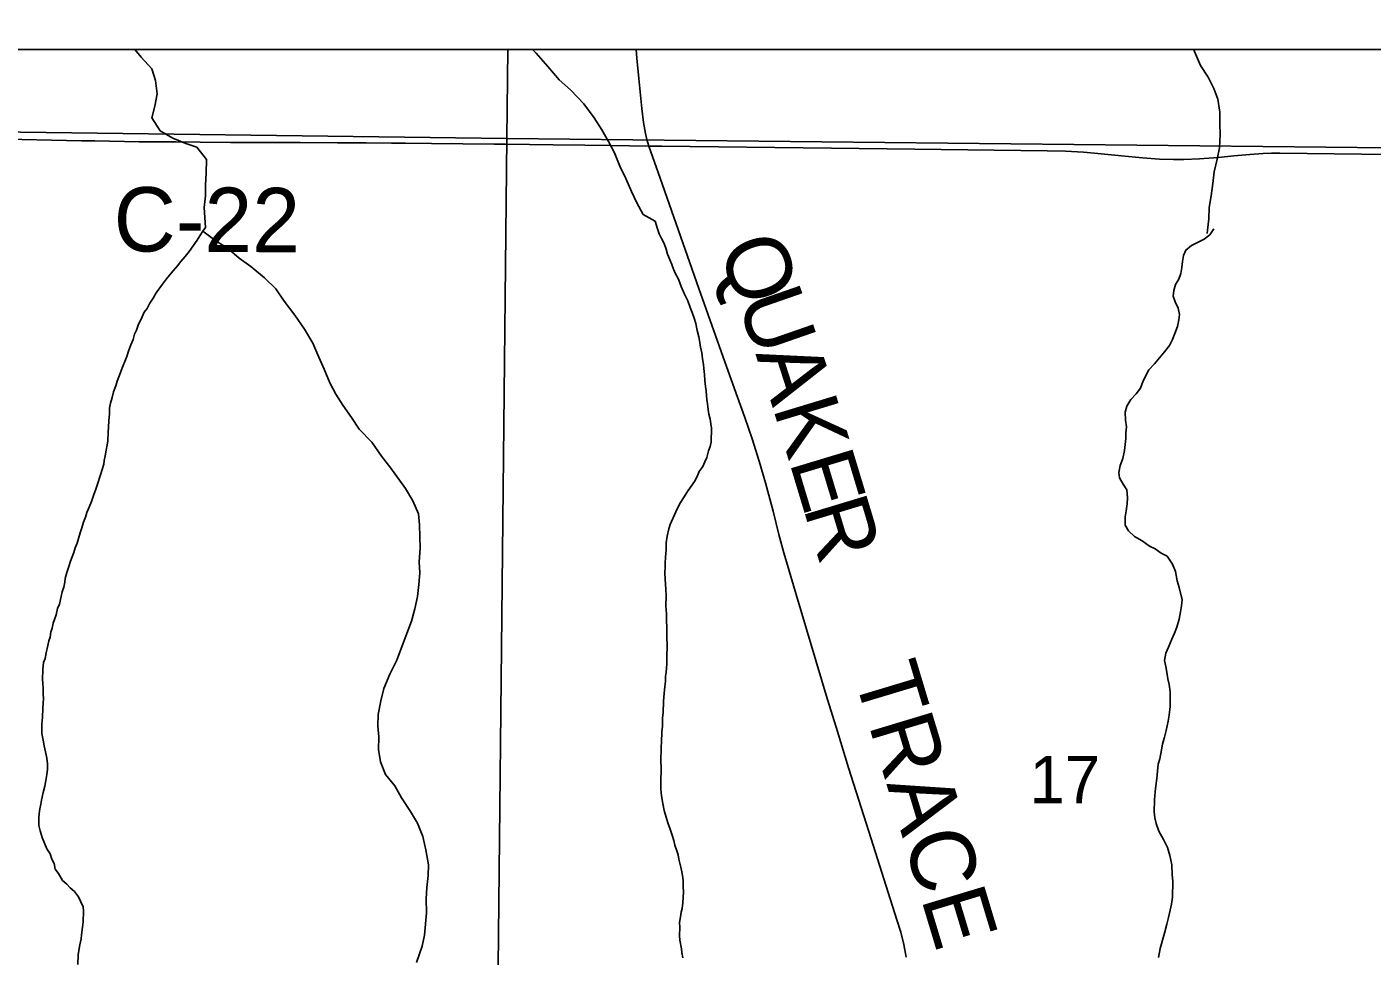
# Model space of a CAD drawing. Extents: x -8.8 to 41.4, y 0 to 34.6.
# Drawn here: x 5.925 to 7.113, y 15.817 to 16.638 of the extents above; entities that cross this region are included whole.
import ezdxf

# ---------------------------------------------------------------- set-up
doc = ezdxf.new("R2010")
doc.units = 0
for name, color, linetype in [('GM_X_Corporation', 7, 'Continuous'), ('GM_X_County_Road', 7, 'Continuous'), ('GM_X_Minor_River', 7, 'Continuous'), ('GM_X_Township_Road_Text', 7, 'Continuous'), ('GM_X_Township_Text', 7, 'Continuous'), ('SH_Data', 7, 'Continuous')]:
    doc.layers.add(name, color=color, linetype=linetype)

msp = doc.modelspace()

# ---------------------------------------------------------------- linework, layer by layer
at = {"layer": 'GM_X_Corporation'}
for points in [[(6.3498, 16.6176), (6.3489, 16.539), (5.354, 16.5519), (5.3707, 17.5614), (6.3609, 17.5464), (6.355, 17.0515)], [(7.3522, 16.6176), (7.351, 16.5283), (6.3489, 16.539), (6.3498, 16.6176)]]:
    msp.add_lwpolyline(points, dxfattribs=at)
for points in [[(5.354, 16.5519), (6.3489, 16.539), (6.3374, 15.4422), (5.3392, 15.4586), (5.3394, 15.5503)], [(6.3489, 16.539), (7.351, 16.5283), (7.3307, 15.4293), (6.3374, 15.4422)]]:
    msp.add_lwpolyline(points, close=True, dxfattribs=at)
at = {"layer": 'GM_X_County_Road'}
for points in [[(6.4745, 16.5323), (6.4727, 16.538), (6.4714, 16.5433), (6.4698, 16.5531), (6.4682, 16.5654), (6.4655, 16.5919), (6.464, 16.6099), (6.4634, 16.6176)], [(5.8938, 16.5388), (5.9733, 16.537), (5.9851, 16.5368), (6.0242, 16.5362), (6.0565, 16.5361), (6.0782, 16.5358), (6.1049, 16.5356), (6.1515, 16.5355), (6.1664, 16.5355), (6.1993, 16.5353), (6.2248, 16.5352), (6.2472, 16.535), (6.2596, 16.5349), (6.2826, 16.5347), (6.3379, 16.534), (6.3478, 16.5339), (6.3689, 16.5337), (6.39, 16.5334), (6.418, 16.5331), (6.4402, 16.5328), (6.4745, 16.5323), (6.486, 16.5322), (6.6357, 16.5305), (6.7096, 16.5296), (6.8264, 16.5281), (6.8425, 16.5277), (6.8586, 16.5268), (6.871, 16.5258), (6.892, 16.5236), (6.9106, 16.5218), (6.9255, 16.5209), (6.9379, 16.5205), (6.9472, 16.5206), (6.9609, 16.5211), (6.9777, 16.5223), (6.9913, 16.5236), (7.0055, 16.5249), (7.0172, 16.5257), (7.0246, 16.526), (7.032, 16.5261), (7.1041, 16.5251), (7.1649, 16.5244)], [(6.7017, 15.8162), (6.6998, 15.8274), (6.6971, 15.8382), (6.6936, 15.849), (6.6688, 15.9271), (6.651, 15.9834), (6.641, 16.0154), (6.6312, 16.0475), (6.6045, 16.1362), (6.5938, 16.1731), (6.5894, 16.1893), (6.5843, 16.2098), (6.5775, 16.235), (6.5719, 16.2541), (6.5658, 16.2737), (6.5594, 16.2926), (6.5529, 16.3107), (6.5417, 16.3417), (6.5186, 16.4066), (6.4844, 16.504), (6.4745, 16.5323)]]:
    msp.add_lwpolyline(points, dxfattribs=at)
at = {"layer": 'GM_X_Minor_River'}
msp.add_line((6.0203, 16.6176), (6.0261, 16.6107), dxfattribs=at)
for points in [[(6.3716, 16.6176), (6.3749, 16.6144), (6.3853, 16.6025), (6.3953, 16.5909), (6.4054, 16.582), (6.417, 16.5697), (6.4262, 16.5573), (6.4328, 16.5466), (6.4387, 16.5363), (6.4442, 16.5263), (6.4489, 16.5145), (6.4541, 16.5037), (6.4592, 16.4923), (6.4639, 16.4823), (6.4694, 16.472), (6.4801, 16.466)], [(6.9559, 16.6176), (6.9566, 16.6157), (6.9617, 16.6035), (6.9687, 16.5931), (6.9735, 16.5832), (6.9771, 16.5736), (6.9788, 16.5622), (6.979, 16.552), (6.9792, 16.5425), (6.9786, 16.5307), (6.9765, 16.5209), (6.974, 16.5096), (6.9727, 16.4994), (6.9714, 16.4884), (6.9696, 16.4782), (6.9691, 16.468), (6.9681, 16.4581), (6.9677, 16.4551)], [(6.0261, 16.6107), (6.0354, 16.6006), (6.0387, 16.5903), (6.04, 16.5785), (6.0379, 16.5676), (6.0354, 16.5574), (6.0428, 16.5459), (6.054, 16.5392), (6.0653, 16.5345), (6.0751, 16.5313), (6.0837, 16.5205), (6.0834, 16.5084), (6.0829, 16.4981), (6.0827, 16.4883), (6.0817, 16.4781)], [(5.996, 16.2684), (5.9965, 16.2718), (5.9967, 16.2801), (5.9972, 16.2839), (5.9974, 16.29), (5.9979, 16.2957), (5.9981, 16.301), (5.999, 16.3052), (6.0003, 16.3104), (6.0015, 16.3153), (6.0036, 16.3206), (6.0048, 16.3247), (6.0069, 16.33), (6.0081, 16.3334), (6.0102, 16.3387), (6.0114, 16.342), (6.0134, 16.3465), (6.0147, 16.3511), (6.0167, 16.3567), (6.0188, 16.3616), (6.02, 16.3661), (6.0217, 16.3699), (6.0237, 16.3751), (6.0261, 16.3796), (6.0286, 16.3856), (6.0313, 16.389), (6.0337, 16.3935), (6.0365, 16.3979), (6.0393, 16.4028), (6.0448, 16.4103), (6.0484, 16.4151), (6.0511, 16.4184), (6.0543, 16.4221), (6.0582, 16.4266), (6.0609, 16.4303), (6.0649, 16.4348), (6.0684, 16.4392), (6.0755, 16.4493), (6.0779, 16.453), (6.0803, 16.4571), (6.0827, 16.4605), (6.0817, 16.4781)], [(6.4801, 16.466), (6.4822, 16.4591)], [(6.0803, 16.4571), (6.0921, 16.4484), (6.1018, 16.4424), (6.1125, 16.4334), (6.1229, 16.4259), (6.1348, 16.416), (6.1448, 16.4063), (6.1524, 16.3954), (6.1616, 16.383), (6.1703, 16.3706), (6.1776, 16.3582), (6.1829, 16.3459), (6.1876, 16.3352), (6.1925, 16.3232), (6.1979, 16.3132), (6.2041, 16.3035), (6.2118, 16.2927), (6.2187, 16.2822), (6.2298, 16.2709), (6.2382, 16.2585), (6.2466, 16.248), (6.2594, 16.2298), (6.2659, 16.219), (6.2709, 16.2075), (6.2718, 16.198), (6.2722, 16.1873), (6.2723, 16.1774), (6.2716, 16.1653), (6.2721, 16.1554), (6.2714, 16.1452), (6.27, 16.1346), (6.2678, 16.1236), (6.2648, 16.1127), (6.2558, 16.0886), (6.2517, 16.0785), (6.2457, 16.0661), (6.2404, 16.0534), (6.2378, 16.0424), (6.2352, 16.0303), (6.2349, 16.0205), (6.2358, 16.0106), (6.2355, 15.9996), (6.2375, 15.9885), (6.2417, 15.9774), (6.2501, 15.9673), (6.2559, 15.9568), (6.2639, 15.9448), (6.2701, 15.9344), (6.2747, 15.9225), (6.2774, 15.911), (6.2797, 15.8977), (6.2794, 15.8882), (6.2784, 15.8776), (6.2777, 15.8677), (6.2781, 15.8552), (6.2764, 15.8355), (6.2743, 15.8257), (6.2693, 15.8114)], [(6.4822, 16.4591), (6.4836, 16.4549), (6.4857, 16.4506), (6.4879, 16.4464), (6.4897, 16.4414), (6.491, 16.4368), (6.4932, 16.4314), (6.4949, 16.4276), (6.4964, 16.4237), (6.4981, 16.4195), (6.5007, 16.4149), (6.5031, 16.4083), (6.506, 16.4014), (6.5088, 16.3956), (6.511, 16.3899), (6.5127, 16.3853), (6.5145, 16.3803), (6.5159, 16.3757), (6.5172, 16.3696), (6.5186, 16.3638), (6.5196, 16.3588), (6.5202, 16.3546), (6.5212, 16.3497), (6.5218, 16.3443), (6.5228, 16.3394), (6.5231, 16.3359), (6.5237, 16.3306), (6.5239, 16.3253), (6.5245, 16.3199), (6.5252, 16.3161), (6.5254, 16.3119), (6.5257, 16.3085), (6.5264, 16.3047), (6.527, 16.2997), (6.5276, 16.2955), (6.5286, 16.2913), (6.5293, 16.2871), (6.5299, 16.2833), (6.5296, 16.2708), (6.5287, 16.267), (6.5271, 16.2633), (6.5258, 16.2572), (6.5238, 16.2535), (6.5221, 16.2493), (6.519, 16.2449), (6.5173, 16.2404), (6.5149, 16.2362), (6.5114, 16.231), (6.5086, 16.2273), (6.505, 16.2217), (6.5023, 16.2176), (6.4999, 16.2127), (6.4982, 16.2094), (6.4934, 16.1981), (6.4921, 16.1943), (6.4908, 16.1879), (6.4899, 16.1819), (6.4897, 16.1758), (6.4891, 16.1693), (6.489, 16.164), (6.4889, 16.1602), (6.4887, 16.1557), (6.489, 16.1496), (6.4892, 16.1458), (6.4895, 16.1408), (6.4897, 16.1355), (6.4894, 16.1264), (6.49, 16.1192), (6.4902, 16.1131), (6.4904, 16.1074), (6.4903, 16.1017), (6.4905, 16.0971), (6.4908, 16.0929), (6.4907, 16.0895), (6.4905, 16.0827), (6.4903, 16.0751), (6.4897, 16.0675), (6.4892, 16.0641), (6.4891, 16.0599), (6.4885, 16.055), (6.488, 16.0489), (6.4874, 16.0421), (6.4871, 16.0318), (6.4866, 16.0273), (6.4864, 16.0201), (6.4859, 16.0152), (6.4856, 16.006), (6.4855, 16.0019), (6.4851, 15.9882), (6.4854, 15.9844), (6.485, 15.9688), (6.4852, 15.9643), (6.4858, 15.9585), (6.4868, 15.9517), (6.4881, 15.9456), (6.4898, 15.9398), (6.4912, 15.9348), (6.4933, 15.9291), (6.4951, 15.9237), (6.4965, 15.9191), (6.4975, 15.9149)], [(6.9736, 16.4592), (6.97, 16.454), (6.965, 16.45), (6.9592, 16.4471), (6.9538, 16.4446), (6.9488, 16.4405), (6.9467, 16.4357), (6.9458, 16.4304), (6.9453, 16.4251), (6.9444, 16.4198), (6.9427, 16.4149), (6.9399, 16.41), (6.9383, 16.4047), (6.9377, 16.3998), (6.9395, 16.3948), (6.942, 16.3891), (6.9434, 16.3837), (6.9428, 16.3788), (6.9415, 16.3731), (6.9391, 16.3667), (6.937, 16.3615), (6.9346, 16.3562), (6.9299, 16.3506), (6.9256, 16.3454), (6.9212, 16.3399), (6.9162, 16.3347), (6.9113, 16.3249), (6.9089, 16.3186), (6.9049, 16.3134), (6.9002, 16.3085), (6.8967, 16.3026), (6.8954, 16.2973), (6.8956, 16.2904), (6.8965, 16.2843), (6.896, 16.279), (6.8958, 16.2741), (6.8948, 16.2635), (6.8931, 16.2563), (6.891, 16.2503), (6.8897, 16.2442), (6.8903, 16.2393), (6.8936, 16.2339), (6.8968, 16.2288), (6.8974, 16.222), (6.8972, 16.2163), (6.8963, 16.2102), (6.8954, 16.2049), (6.8952, 16.1977), (6.8981, 16.1927), (6.9036, 16.1876), (6.9104, 16.1836), (6.9167, 16.1789), (6.9219, 16.1768), (6.9271, 16.1729), (6.9324, 16.1701), (6.9371, 16.1631), (6.9399, 16.1566), (6.9412, 16.1485), (6.943, 16.1424), (6.9457, 16.1317), (6.9452, 16.1264), (6.9443, 16.1211), (6.9429, 16.1147), (6.9408, 16.1075), (6.9388, 16.1023), (6.9364, 16.097), (6.9335, 16.0899), (6.9311, 16.0846), (6.9301, 16.0782), (6.9311, 16.0728), (6.9321, 16.0679), (6.9331, 16.0618), (6.9341, 16.0568), (6.935, 16.0503), (6.9349, 16.0454), (6.935, 16.0374), (6.9341, 16.0298), (6.9332, 16.0245), (6.9314, 16.0162), (6.9301, 16.0105), (6.9284, 16.0041), (6.9275, 15.9992), (6.9258, 15.9913), (6.9245, 15.9864), (6.9239, 15.9803), (6.9234, 15.9739), (6.9224, 15.9674), (6.9219, 15.9621), (6.9213, 15.9549), (6.921, 15.9443), (6.9216, 15.939), (6.9226, 15.934), (6.9251, 15.9275), (6.9291, 15.9201), (6.9326, 15.9128), (6.9347, 15.9059), (6.9364, 15.8975), (6.9369, 15.8891), (6.9375, 15.883), (6.9371, 15.869), (6.9362, 15.8629)], [(5.9701, 15.8097), (5.9703, 15.8181), (5.9713, 15.8237), (5.9717, 15.8271), (5.973, 15.8324), (5.9731, 15.8358), (5.9741, 15.8427), (5.9746, 15.8472), (5.9749, 15.8567), (5.9746, 15.8605), (5.9724, 15.8655), (5.9707, 15.8694), (5.967, 15.874), (5.9633, 15.8772), (5.9604, 15.8807), (5.9566, 15.8838), (5.953, 15.89), (5.9501, 15.8939), (5.9491, 15.8988), (5.9469, 15.9027), (5.9456, 15.9073), (5.9427, 15.9119), (5.9384, 15.9219), (5.9366, 15.9277), (5.9356, 15.9323), (5.9355, 15.9391), (5.9359, 15.9429), (5.9364, 15.9471), (5.9373, 15.9512), (5.9378, 15.9546), (5.9395, 15.9614), (5.9408, 15.9671), (5.9417, 15.972), (5.9426, 15.9773), (5.9431, 15.9818), (5.9433, 15.9868), (5.9426, 15.9917), (5.9413, 15.9975), (5.9403, 16.0028), (5.9393, 16.0078), (5.9383, 16.0135), (5.9381, 16.0173), (5.9382, 16.0219), (5.9387, 16.0276), (5.939, 16.0359), (5.9395, 16.0405), (5.9396, 16.0446), (5.9393, 16.0484), (5.9395, 16.0534), (5.9392, 16.0579), (5.9389, 16.0614), (5.9392, 16.0701), (5.9397, 16.0762), (5.941, 16.0799), (5.9419, 16.0849), (5.9436, 16.0913), (5.9444, 16.0954), (5.9457, 16.0988), (5.9462, 16.103), (5.9474, 16.1067), (5.9483, 16.1109), (5.9495, 16.1143), (5.9508, 16.1184), (5.9521, 16.1241), (5.9537, 16.1278), (5.9554, 16.1346), (5.9563, 16.1388), (5.9576, 16.1429), (5.9584, 16.1471), (5.9589, 16.1505), (5.9602, 16.1558), (5.9622, 16.161), (5.9635, 16.1659), (5.9651, 16.1697), (5.9664, 16.1735), (5.9676, 16.1776), (5.9693, 16.1817), (5.9705, 16.1859), (5.9722, 16.1908), (5.9735, 16.1953), (5.9751, 16.2002), (5.9768, 16.2047), (5.978, 16.2088), (5.98, 16.2134), (5.9821, 16.2186), (5.9838, 16.2239), (5.9858, 16.2295), (5.9874, 16.2337), (5.99, 16.2419), (5.9916, 16.2468), (5.9929, 16.2514), (5.9934, 16.2548), (5.9942, 16.2589), (5.9951, 16.2638), (5.996, 16.2684)], [(6.4975, 15.9149), (6.4992, 15.9099), (6.5003, 15.9064), (6.5009, 15.9026), (6.5026, 15.8957), (6.5036, 15.8915), (6.5043, 15.8881), (6.5049, 15.8839), (6.5048, 15.8786), (6.505, 15.8736), (6.5049, 15.8691), (6.5044, 15.8642), (6.5039, 15.8592), (6.503, 15.8558), (6.5025, 15.8517), (6.5016, 15.8468), (6.5019, 15.8426), (6.5017, 15.835), (6.5019, 15.8312), (6.5032, 15.8235), (6.5035, 15.8201), (6.5045, 15.8155)], [(6.9362, 15.8629), (6.9349, 15.8577), (6.9336, 15.8512), (6.9322, 15.8452), (6.9301, 15.8373), (6.9263, 15.8237), (6.9246, 15.8158)]]:
    msp.add_lwpolyline(points, dxfattribs=at)
at = {"layer": 'SH_Data'}
msp.add_lwpolyline([(5.4782, 17.0515), (7.5548, 17.0515), (7.5548, 16.6176), (5.4782, 16.6176)], close=True, dxfattribs=at)

# ---------------------------------------------------------------- texts
at = {"layer": 'GM_X_Township_Road_Text'}
for s, height, rotation, p in [('C-22', 0.05682, 359.6571, (6.0015, 16.4394)), ('Q', 0.0568, 289.8451, (6.5353, 16.4428)), ('U', 0.0568, 289.1532, (6.5522, 16.3959)), ('A', 0.0568, 287.8584, (6.5685, 16.349)), ('K', 0.0568, 286.8831, (6.5838, 16.3016)), ('E', 0.0568, 286.7969, (6.5983, 16.2538)), ('R', 0.0568, 286.799, (6.6106, 16.2131)), ('TRACE', 0.05682, 286.7795, (6.655, 16.0662))]:
    msp.add_text(s, height=height, rotation=rotation, dxfattribs=at).set_placement(p)
at = {"layer": 'GM_X_Township_Text'}
msp.add_text('17', height=0.04186, rotation=0, dxfattribs=at).set_placement((6.8109, 15.952))

doc.saveas('drawing.dxf')
